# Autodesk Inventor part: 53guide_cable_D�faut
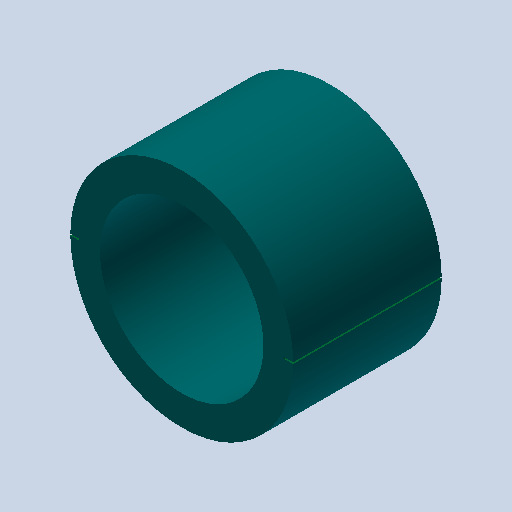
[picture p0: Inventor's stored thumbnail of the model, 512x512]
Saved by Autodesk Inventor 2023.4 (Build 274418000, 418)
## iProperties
Created: 2011-01
Part Number: 53guide_cable_D�faut
Document SubType Name: Modeling
Designer: eric
Density: 1 g/cm^3
Mass: 0.815615 g
Surface Area: 10.0394 cm^2
Volume: 0.815615 cm^3
Material: Générique
Appearance: 0,128,64
Author: eric
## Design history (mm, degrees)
feature "Base1"
node "Corps solides"
node "Corps surfaciques"
node "Solide1"
